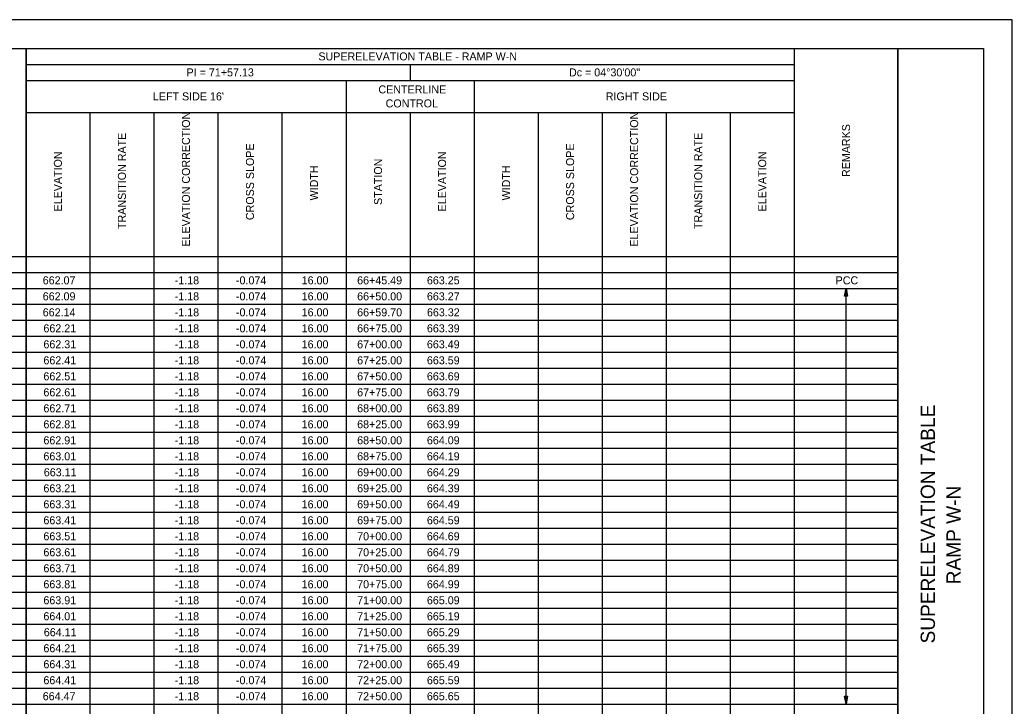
# Model space of a CAD drawing. Extents: x 0 to 34, y 0 to 22.
# Drawn here: x 16.64 to 34, y 9.99 to 22 of the extents above; entities that cross this region are included whole.
import ezdxf

# ---------------------------------------------------------------- set-up
doc = ezdxf.new("R2010")
doc.units = 0
for name, color, linetype in [('SH_Border', 7, 'Continuous'), ('SH_Cut_Line', 7, 'Continuous'), ('SH_Data', 7, 'Continuous'), ('SH_Text', 7, 'Continuous')]:
    doc.layers.add(name, color=color, linetype=linetype)

msp = doc.modelspace()

# ---------------------------------------------------------------- linework, layer by layer
at = {"layer": 'SH_Border'}
msp.add_line((32, 0.5), (32, 21.5), dxfattribs=at)
msp.add_lwpolyline([(1.5, 21.5), (33.5, 21.5), (33.5, 0.5), (1.5, 0.5)], close=True, dxfattribs=at)
at = {"layer": 'SH_Cut_Line'}
msp.add_lwpolyline([(0, 0), (34, 0), (34, 22), (0, 22)], close=True, dxfattribs=at)
at = {"layer": 'SH_Text'}
for p, q in [((1.5, 21.5), (16.752, 21.5)), ((16.748, 21.5), (32, 21.5)), ((16.748, 21.5), (16.748, 0.5)), ((16.752, 21.5), (16.752, 0.5)), ((30.188, 21.5), (30.188, 0.5)), ((32, 21.5), (32, 0.5)), ((16.748, 21.22), (30.188, 21.22)), ((23.468, 21.22), (23.468, 20.94)), ((16.748, 20.94), (30.188, 20.94)), ((22.348, 20.94), (22.348, 0.5)), ((24.588, 20.94), (24.588, 0.5)), ((16.748, 20.38), (30.188, 20.38)), ((17.868, 20.38), (17.868, 0.5)), ((18.988, 20.38), (18.988, 0.5)), ((20.108, 20.38), (20.108, 0.5)), ((21.228, 20.38), (21.228, 0.5)), ((23.468, 20.38), (23.468, 0.5)), ((25.708, 20.38), (25.708, 0.5)), ((26.828, 20.38), (26.828, 0.5)), ((27.948, 20.38), (27.948, 0.5)), ((29.068, 20.38), (29.068, 0.5)), ((1.5, 17.86), (16.752, 17.86)), ((16.748, 17.86), (32, 17.86)), ((1.5, 17.58), (16.752, 17.58)), ((16.748, 17.58), (32, 17.58)), ((1.5, 17.3), (16.752, 17.3)), ((16.748, 17.3), (32, 17.3)), ((31.094, 10.02), (31.094, 17.3)), ((1.5, 17.02), (16.752, 17.02)), ((16.748, 17.02), (32, 17.02)), ((1.5, 16.74), (16.752, 16.74)), ((16.748, 16.74), (32, 16.74)), ((1.5, 16.46), (16.752, 16.46)), ((16.748, 16.46), (32, 16.46)), ((1.5, 16.18), (16.752, 16.18)), ((16.748, 16.18), (32, 16.18)), ((1.5, 15.9), (16.752, 15.9)), ((16.748, 15.9), (32, 15.9)), ((1.5, 15.62), (16.752, 15.62)), ((16.748, 15.62), (32, 15.62)), ((1.5, 15.34), (16.752, 15.34)), ((16.748, 15.34), (32, 15.34)), ((1.5, 15.06), (16.752, 15.06)), ((16.748, 15.06), (32, 15.06)), ((1.5, 14.78), (16.752, 14.78)), ((16.748, 14.78), (32, 14.78)), ((1.5, 14.5), (16.752, 14.5)), ((16.748, 14.5), (32, 14.5)), ((1.5, 14.22), (16.752, 14.22)), ((16.748, 14.22), (32, 14.22)), ((1.5, 13.94), (16.752, 13.94)), ((16.748, 13.94), (32, 13.94)), ((1.5, 13.66), (16.752, 13.66)), ((16.748, 13.66), (32, 13.66)), ((1.5, 13.38), (16.752, 13.38)), ((16.748, 13.38), (32, 13.38)), ((1.5, 13.1), (16.752, 13.1)), ((16.748, 13.1), (32, 13.1)), ((1.5, 12.82), (16.752, 12.82)), ((16.748, 12.82), (32, 12.82)), ((1.5, 12.54), (16.752, 12.54)), ((16.748, 12.54), (32, 12.54)), ((1.5, 12.26), (16.752, 12.26)), ((16.748, 12.26), (32, 12.26)), ((1.5, 11.98), (16.752, 11.98)), ((16.748, 11.98), (32, 11.98)), ((1.5, 11.7), (16.752, 11.7)), ((16.748, 11.7), (32, 11.7)), ((1.5, 11.42), (16.752, 11.42)), ((16.748, 11.42), (32, 11.42)), ((1.5, 11.14), (16.752, 11.14)), ((16.748, 11.14), (32, 11.14)), ((1.5, 10.86), (16.752, 10.86)), ((16.748, 10.86), (32, 10.86)), ((1.5, 10.58), (16.752, 10.58)), ((16.748, 10.58), (32, 10.58)), ((1.5, 10.3), (16.752, 10.3)), ((16.748, 10.3), (32, 10.3)), ((1.5, 10.02), (16.752, 10.02)), ((16.748, 10.02), (32, 10.02))]:
    msp.add_line(p, q, dxfattribs=at)
for points in [[(31.066, 17.16), (31.094, 17.3), (31.122, 17.16)], [(31.122, 10.16), (31.094, 10.02), (31.066, 10.16)]]:
    msp.add_lwpolyline(points, close=True, dxfattribs=at)

# ---------------------------------------------------------------- texts
at = {"layer": 'SH_Data'}
for s, p in [('SUPERELEVATION TABLE', (32.65, 11.084)), ('RAMP W-N', (33.1, 12.118))]:
    msp.add_text(s, height=0.25, rotation=90, dxfattribs=at).set_placement(p)
at = {"layer": 'SH_Text'}
for s, p in [('SUPERELEVATION TABLE - RAMP W-N', (21.865, 21.29)), ('PI = 71+57.13', (19.559, 21.01)), ('Dc = 04°30\'00"', (26.248, 21.01)), ('CENTERLINE', (22.915, 20.712)), ("LEFT SIDE 16'", (18.97, 20.59)), ('RIGHT SIDE', (26.891, 20.59)), ('CONTROL', (23.041, 20.467)), ('662.07', (17.043, 17.37)), ('-1.18', (19.352, 17.37)), ('-0.074', (20.423, 17.37)), ('16.00', (21.572, 17.37)), ('66+45.49', (22.543, 17.37)), ('663.25', (23.763, 17.37)), ('PCC', (30.912, 17.37)), ('662.09', (17.043, 17.09)), ('-1.18', (19.352, 17.09)), ('-0.074', (20.423, 17.09)), ('16.00', (21.572, 17.09)), ('66+50.00', (22.543, 17.09)), ('663.27', (23.763, 17.09)), ('662.14', (17.043, 16.81)), ('-1.18', (19.352, 16.81)), ('-0.074', (20.423, 16.81)), ('16.00', (21.572, 16.81)), ('66+59.70', (22.543, 16.81)), ('663.32', (23.764, 16.81)), ('662.21', (17.055, 16.53)), ('-1.18', (19.352, 16.53)), ('-0.074', (20.423, 16.53)), ('16.00', (21.572, 16.53)), ('66+75.00', (22.543, 16.53)), ('663.39', (23.763, 16.53)), ('662.31', (17.055, 16.25)), ('-1.18', (19.352, 16.25)), ('-0.074', (20.423, 16.25)), ('16.00', (21.572, 16.25)), ('67+00.00', (22.543, 16.25)), ('663.49', (23.763, 16.25)), ('662.41', (17.055, 15.97)), ('-1.18', (19.352, 15.97)), ('-0.074', (20.423, 15.97)), ('16.00', (21.572, 15.97)), ('67+25.00', (22.543, 15.97)), ('663.59', (23.763, 15.97)), ('662.51', (17.055, 15.69)), ('-1.18', (19.352, 15.69)), ('-0.074', (20.423, 15.69)), ('16.00', (21.572, 15.69)), ('67+50.00', (22.543, 15.69)), ('663.69', (23.763, 15.69)), ('662.61', (17.055, 15.41)), ('-1.18', (19.352, 15.41)), ('-0.074', (20.423, 15.41)), ('16.00', (21.572, 15.41)), ('67+75.00', (22.543, 15.41)), ('663.79', (23.763, 15.41)), ('662.71', (17.055, 15.13)), ('-1.18', (19.352, 15.13)), ('-0.074', (20.423, 15.13)), ('16.00', (21.572, 15.13)), ('68+00.00', (22.543, 15.13)), ('663.89', (23.763, 15.13)), ('662.81', (17.055, 14.85)), ('-1.18', (19.352, 14.85)), ('-0.074', (20.423, 14.85)), ('16.00', (21.572, 14.85)), ('68+25.00', (22.543, 14.85)), ('663.99', (23.763, 14.85)), ('662.91', (17.055, 14.57)), ('-1.18', (19.352, 14.57)), ('-0.074', (20.423, 14.57)), ('16.00', (21.572, 14.57)), ('68+50.00', (22.543, 14.57)), ('664.09', (23.763, 14.57)), ('663.01', (17.055, 14.29)), ('-1.18', (19.352, 14.29)), ('-0.074', (20.423, 14.29)), ('16.00', (21.572, 14.29)), ('68+75.00', (22.543, 14.29)), ('664.19', (23.763, 14.29)), ('663.11', (17.062, 14.01)), ('-1.18', (19.352, 14.01)), ('-0.074', (20.423, 14.01)), ('16.00', (21.572, 14.01)), ('69+00.00', (22.543, 14.01)), ('664.29', (23.763, 14.01)), ('663.21', (17.055, 13.73)), ('-1.18', (19.352, 13.73)), ('-0.074', (20.423, 13.73)), ('16.00', (21.572, 13.73)), ('69+25.00', (22.543, 13.73)), ('664.39', (23.763, 13.73)), ('663.31', (17.055, 13.45)), ('-1.18', (19.352, 13.45)), ('-0.074', (20.423, 13.45)), ('16.00', (21.572, 13.45)), ('69+50.00', (22.543, 13.45)), ('664.49', (23.763, 13.45)), ('663.41', (17.055, 13.17)), ('-1.18', (19.352, 13.17)), ('-0.074', (20.423, 13.17)), ('16.00', (21.572, 13.17)), ('69+75.00', (22.543, 13.17)), ('664.59', (23.763, 13.17)), ('663.51', (17.055, 12.89)), ('-1.18', (19.352, 12.89)), ('-0.074', (20.423, 12.89)), ('16.00', (21.572, 12.89)), ('70+00.00', (22.543, 12.89)), ('664.69', (23.763, 12.89)), ('663.61', (17.055, 12.61)), ('-1.18', (19.352, 12.61)), ('-0.074', (20.423, 12.61)), ('16.00', (21.572, 12.61)), ('70+25.00', (22.543, 12.61)), ('664.79', (23.763, 12.61)), ('663.71', (17.055, 12.33)), ('-1.18', (19.352, 12.33)), ('-0.074', (20.423, 12.33)), ('16.00', (21.572, 12.33)), ('70+50.00', (22.543, 12.33)), ('664.89', (23.763, 12.33)), ('663.81', (17.055, 12.05)), ('-1.18', (19.352, 12.05)), ('-0.074', (20.423, 12.05)), ('16.00', (21.572, 12.05)), ('70+75.00', (22.543, 12.05)), ('664.99', (23.763, 12.05)), ('663.91', (17.055, 11.77)), ('-1.18', (19.352, 11.77)), ('-0.074', (20.423, 11.77)), ('16.00', (21.572, 11.77)), ('71+00.00', (22.543, 11.77)), ('665.09', (23.763, 11.77)), ('664.01', (17.055, 11.49)), ('-1.18', (19.352, 11.49)), ('-0.074', (20.423, 11.49)), ('16.00', (21.572, 11.49)), ('71+25.00', (22.543, 11.49)), ('665.19', (23.763, 11.49)), ('664.11', (17.062, 11.21)), ('-1.18', (19.352, 11.21)), ('-0.074', (20.423, 11.21)), ('16.00', (21.572, 11.21)), ('71+50.00', (22.543, 11.21)), ('665.29', (23.763, 11.21)), ('664.21', (17.055, 10.93)), ('-1.18', (19.352, 10.93)), ('-0.074', (20.423, 10.93)), ('16.00', (21.572, 10.93)), ('71+75.00', (22.543, 10.93)), ('665.39', (23.763, 10.93)), ('664.31', (17.055, 10.65)), ('-1.18', (19.352, 10.65)), ('-0.074', (20.423, 10.65)), ('16.00', (21.572, 10.65)), ('72+00.00', (22.543, 10.65)), ('665.49', (23.763, 10.65)), ('664.41', (17.055, 10.37)), ('-1.18', (19.352, 10.37)), ('-0.074', (20.423, 10.37)), ('16.00', (21.572, 10.37)), ('72+25.00', (22.543, 10.37)), ('665.59', (23.763, 10.37)), ('664.47', (17.043, 10.09)), ('-1.18', (19.352, 10.09)), ('-0.074', (20.423, 10.09)), ('16.00', (21.572, 10.09)), ('72+50.00', (22.543, 10.09)), ('665.65', (23.763, 10.09))]:
    msp.add_text(s, height=0.14, dxfattribs=at).set_placement(p)
for s, p in [('ELEVATION CORRECTION', (19.618, 18.03)), ('ELEVATION CORRECTION', (27.458, 18.03)), ('REMARKS', (31.164, 19.249)), ('TRANSITION RATE', (18.498, 18.339)), ('TRANSITION RATE', (28.578, 18.339)), ('CROSS SLOPE', (20.738, 18.494)), ('CROSS SLOPE', (26.338, 18.494)), ('ELEVATION', (17.378, 18.646)), ('ELEVATION', (24.098, 18.646)), ('ELEVATION', (29.698, 18.646)), ('STATION', (22.978, 18.759)), ('WIDTH', (21.858, 18.839)), ('WIDTH', (25.218, 18.839))]:
    msp.add_text(s, height=0.14, rotation=90, dxfattribs=at).set_placement(p)

doc.saveas('drawing.dxf')
